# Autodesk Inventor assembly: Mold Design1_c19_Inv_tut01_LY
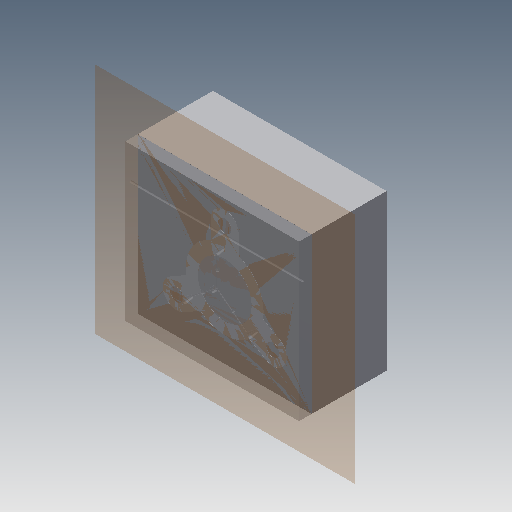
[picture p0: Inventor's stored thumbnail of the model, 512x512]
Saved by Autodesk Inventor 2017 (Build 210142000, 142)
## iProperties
Created: 2016-07
Part Number: Mold Design1_c19_Inv_tut01_LY
Document SubType Name: Assembly
Designer: Sandeep
Author: Sandeep
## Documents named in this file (2)
- C:\Inventor_2017\c19\Mold Design1_c19_Inv_tut01_LY.iam
- C:\Inventor_2017\c19\Mold Design1_c19_Inv_tut01_PZ.iam
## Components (1 placed, 1 different names)
1. Mold Design1_c19_Inv_tut01_PZ:1 [sub-assembly] — Flush:1, Flush:2, Flush:3
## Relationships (3: Flush 3)
- Flush:1: Mold Design1_c19_Inv_tut01_PZ:1
- Flush:2: Mold Design1_c19_Inv_tut01_PZ:1
- Flush:3: Mold Design1_c19_Inv_tut01_PZ:1
